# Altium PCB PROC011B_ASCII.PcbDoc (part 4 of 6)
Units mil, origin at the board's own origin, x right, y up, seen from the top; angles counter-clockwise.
Board outline 3304 x 2569 mil, 6 copper layers (TOP, L2-GND1, L3-GND/SIG, L4-GND/SIG, L5-GND2, BOTTOM), stack 55.77 mil thick; 376 components, 289 nets, 1284 pads, 1755 vias.
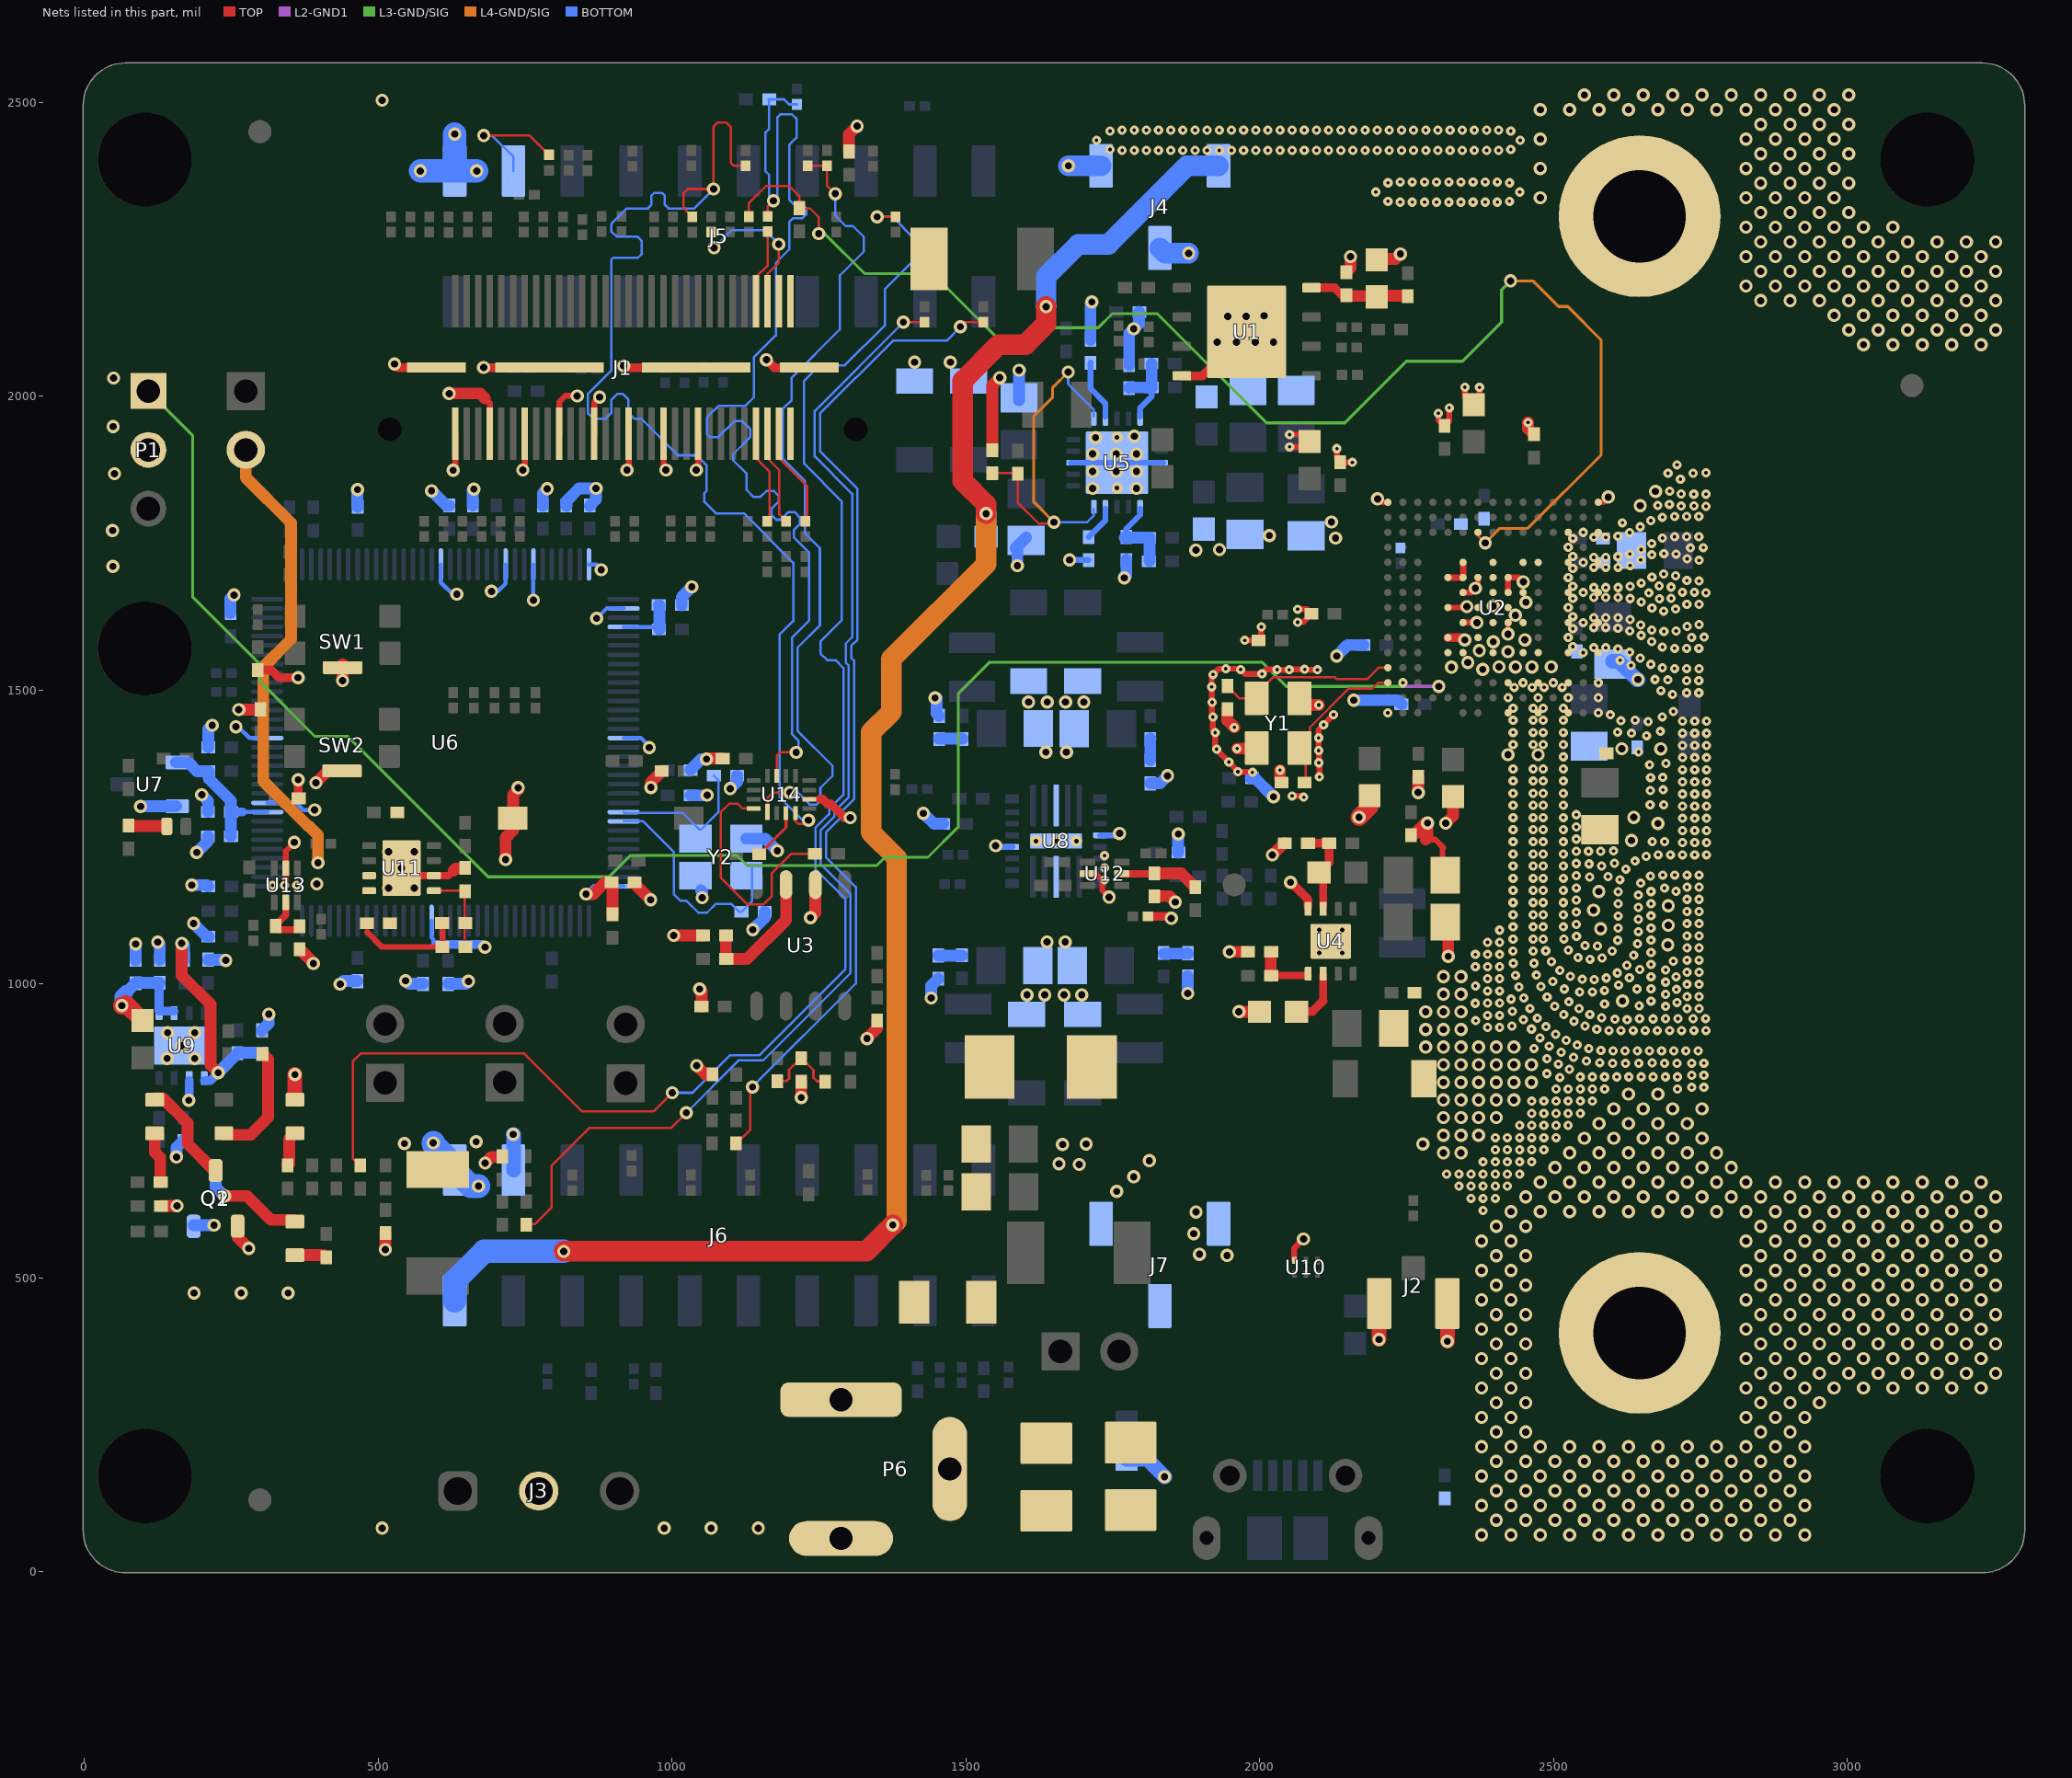
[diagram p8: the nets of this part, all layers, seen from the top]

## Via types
v1: diameter 22.4, hole 12.2, TOP to BOTTOM, tented both sides, 1046 vias
v2: diameter 15.74, hole 5.9, TOP to L2-GND1, tented both sides, 700 vias
v3: diameter 19.68, hole 7.87, TOP to BOTTOM, tented both sides, 9 vias

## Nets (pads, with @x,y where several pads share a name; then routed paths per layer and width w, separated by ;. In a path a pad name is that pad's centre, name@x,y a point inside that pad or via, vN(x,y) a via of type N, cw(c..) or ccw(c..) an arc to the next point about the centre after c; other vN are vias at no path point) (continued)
AR_VSENSE: P1.1 U2.C14 | length 3095.5
  L2-GND1 w5: v2(2243.76,1512.45) 2249.91,1506.3 v1(2304.85,1506.3)
  L3-GND/SIG w5: P1.1@109.02,2008.65 184.25,1933.42 184.25,1658.5 297.95,1544.8 297.95,1515.3 391.75,1421.5 447.65,1421.5 686.85,1182.3 893.05,1182.3 929.45,1218.7 1079.78,1218.7 1079.92,1218.56 1110.25,1218.56 1127.41,1201.4 1348.65,1201.4 1362.72,1215.47 1435.53,1215.47 1487.45,1267.39 1487.45,1494.47 1540.13,1547.15 2004.69,1547.15 2045.54,1506.3 v1(2304.85,1506.3)
AR_WARMRST: R15.1 R18.1 U2.N9 | length 2374.3
  TOP w4: R18.1@1130.96,2305.56 1130.96,2328.72 1159.74,2357.5 1199.74,2357.5 1216.75,2340.49 R15.1@1216.75,2320.04 1216.75,2319.25 1234.99,2319.25 1249.75,2304.49 v1(1249.75,2276.5) ; U2.N9@2371.71,1768.35 2371.71,1762.58 v1(2383.94,1750.35)
  L3-GND/SIG w5: v1(1249.75,2276.5) 1259.75,2276.5 1327.75,2208.5 1443.74,2208.5 1511.74,2140.5 1561.75,2090.5 1624.55,2090.5 1650.75,2116.7 1725.55,2116.7 1749.35,2140.5 1825.65,2140.5 2011.65,1954.5 2144.85,1954.5 2249.85,2059.5 2345.25,2059.5 2411.75,2126 2411.75,2181 v1(2426.95,2196.2)
  L4-GND/SIG w5: v1(2383.94,1750.35) 2408.69,1775.1 2456.15,1775.1 2581.15,1900.1 2581.15,2095.7 2524.35,2152.5 2508.95,2152.5 2465.25,2196.2 v1(2426.95,2196.2)
AR_XTALM: C9.2 U2.D15 Y1.1 | length 310.5
  TOP w4: C9.2@1945.11,1506.53 1965.68,1485.96 Y1.1@1995.05,1485.96 1995.05,1494.1 2022.55,1521.6 2128.25,1521.6 2131.35,1518.5 2182.76,1518.5 2202.3,1538.04 U2.D15@2218.17,1538.04
AR_XTALP: C15.2 U2.C15 Y1.3 | length 269.3
  TOP w4: C15.2@2078.45,1342.9 2078.28,1343.07 2078.28,1390.93 Y1.3@2067.89,1401.32 2085.45,1418.88 2085.45,1436.2 2151.75,1502.5 2191.75,1502.5 2201.7,1512.45 U2.C15@2218.17,1512.45
CAN_RX: R12.1 U14.3 | length 88.9
  TOP w5: R12.1@1148.6,1220.7 1148.6,1220.88 1194.14,1266.43 U14.3@1194.14,1290.71
CAN_TX: R11.1 U14.16 | length 414.6
  TOP w4: U14.16@1139.03,1298.59 1119.85,1298.59 1111.77,1306.66 1097.53,1306.66 1082.75,1291.88 1082.75,1181.16 1128.82,1135.09 1155.63,1135.09 1170.22,1149.68 1170.22,1188.61 1203.03,1221.42 R11.1@1243.26,1221.42
CS1: R1.2 R14.1 R17.1 U14.11 | length 2014.1
  TOP w4: R17.1@1163,2306.21 1163,2322.75 v1(1172.75,2332.5) ; U14.11@1178.4,1353.71 1178.4,1388.61 1183.82,1394.03 v1(1211.3,1394.03)
  BOTTOM w4: R14.1@1164.55,2505.1 1164.94,2504.71 R14.1@1165.33,2504.32 ; v1(1211.3,1394.03) 1215.55,1398.28 1215.55,1413.8 1204.58,1424.77 1204.58,1589.33 1233.65,1618.4 1233.65,1733.6 1207.37,1759.88 1207.37,1771.75 1217.45,1781.83 1217.45,1793.84 1208.44,1802.85 1198.4,1802.85 1185.43,1789.88 1177.37,1789.88 1169.46,1797.79 1169.46,1808.62 1181.52,1820.68 1181.52,1830.71 1173.46,1838.77 1160.66,1838.77 1150.25,1828.36 1138.89,1828.36 1126.93,1840.32 1126.93,1867.97 1104.17,1890.73 1104.17,1901.36 1133.26,1930.45 1133.26,1943.7 1118.91,1958.05 1106.58,1958.05 1079.08,1930.56 1064.35,1930.56 1059.53,1935.37 1059.53,1964.01 1079.32,1983.8 1125.15,1983.8 1139.72,1998.38 1139.72,2066.57 1176.75,2103.6 1176.75,2226.9 1199.45,2249.6 1199.45,2295.83 1206.59,2302.97 1222.11,2302.97 1228.57,2309.43 1228.57,2319.78 1221.17,2327.18 1206.59,2327.18 1199.45,2334.32 1199.45,2427.51 1212.05,2440.11 1212.05,2471.94 1204.37,2479.62 1184.3,2479.62 1179.41,2474.73 1179.41,2339.16 v1(1172.75,2332.5) 1165.33,2339.92 1165.33,2376.39 1159.09,2382.63 1159.09,2448.81 1165.33,2455.05 R14.1@1165.33,2504.32 ; R14.1@1165.33,2504.32 R14.1@1165.33,2505.1 1190.75,2505.1 1199.34,2496.51 ; 1199.34,2496.51 R1.2@1212.55,2496.51 1199.34,2496.51
D_LOGGER: J5.4 R60.1 | length 214.1
  TOP w4: v1(679.75,2443.5) 757.74,2443.5 R60.1@790.75,2410.49
  BOTTOM w4: v1(679.75,2443.5) 693.75,2443.5 730.25,2407 J5.4@730.25,2383.22
GND: C1.1 C2.1 C3.1 C4.1 C5.1 C6.1 C7.1 C8.1 C9.1 C10.1 C11.1 C12.1 C13.1 C14.1 C15.1 C16.1 C17.1 C19.1 C20.1 C21.1 C22.1 C23.1 C24.1 C25.1 C26.2 C27.2 C29.1 C30.1 C31.1 C32.1 C33.1 C34.1 C35.1 C36.1 C37.1 C38.1 C39.1 C40.1 C41.1 C42.1 C43.1 C44.1 C45.1 C47.1 C48.1 C49.1 C50.1 C51.1 C52.1 C53.1 C54.1 C55.1 C56.1 C57.1 C58.1 C59.1 C60.1 C61.1 C62.1 C63.1 C64.1 C65.1 C66.1 C67.1 C68.1 C69.1 C70.1 C71.1 C72.1 C73.1 C74.1 C75.1 C76.1 C77.1 C79.1 C80.1 C81.1 C82.1 C83.1 C84.1 C85.1 C86.1 C87.1 C89.1 C90.1 C91.1 C92.1 C93.1 C94.1 C95.1 C96.1 C97.1 D3.2 DS2.2 J1.18 J1.24 J1.30 J1.36 J1.42 J1.48 J1.54 J1.60 J1.MP1 J1.MP2 J1.MP3 J1.MP4 J2.2 J2.3 J3.2 J4.1 J4.2 J5.2 J6.4 J7.1 J7.2 P1.2 P6.2 P6.3 pad.1 pad.2 Q1.2 Q2.2 R13.1 R47.2 R73.1 R79.1 R81.1 R83.2 R86.2 R88.1 R96.1 R110.1 R114.1 R119.1 R121.1 R123.2 R125.1 R126.2 R132.1 R138.1 R139.1 R153.1 R157.1 R158.1 R167.1 R174.1 R175.1 R193.1 R208.2 S2.1 SW1.5 SW2.5 U1.4 U1.9 U2.A1 U2.A3 U2.A5 U2.A7 U2.A15 U2.B1 U2.B3 U2.B5 U2.B7 U2.C1 U2.C3 U2.C4 U2.C5 U2.C6 U2.C7 U2.E1 U2.E2 U2.E3 U2.E5 U2.E6 U2.E8 U2.E10 U2.E11 U2.F3 U2.F9 U2.F11 U2.G1 U2.G2 U2.G3 U2.G6 U2.G7 U2.G8 U2.G10 U2.H3 U2.H7 U2.H9 U2.H11 U2.J1 U2.J2 U2.J3 U2.J6 U2.J7 U2.J8 U2.J10 U2.K3 U2.K7 U2.K8 U2.K9 U2.K10 U2.K11 U2.L1 U2.L2 U2.L3 U2.L5 U2.L6 U2.L8 U2.L10 U2.M3 U2.N1 U2.N2 U2.N3 U2.R1 U2.R15 U3.2 U4.4 U4.9 U5.3 U5.13 U5.21@1757.37,1886.82 U6.10 U6.17 U6.48 U6.55 U6.58 U6.64 U6.66 U6.80 U6.114 U7.2 U8.4 U8.11 U8.17 U8.24 U8.27 U9.6 U9.9 U10.3 U11.6 U11.9 U12.2 U13.2 U14.6 Y1.2 Y1.4 Y2.2 Y2.4 | length 8140.2
  TOP w7: U14.6@1233.51,1314.34 1252.42,1314.34 ; U2.J7@2421.64,1665.99 U2.J7@2422.89,1665.99 U2.J7@2423.36,1665.99 ; U2.G7@2422.89,1614.81 U2.G7@2422.89,1614.81 v1@2422.89,1595.21
  TOP w9: v1(2367.2,1673.3) 2371.71,1677.81 U2.K9@2371.71,1691.58
  TOP w10: v2@342.75,1175.5 342.75,1226.3 v1(357.35,1240.9) ; v1(627.73,1874.03) 631.37,1877.67 J1.60@631.37,1935.77 ; 681.75,1996.5 690.42,1987.83 J1.54@690.42,1935.77 ; v1(746.28,1874.47) 749.48,1877.67 J1.48@749.48,1935.77 ; J1.42@808.53,1935.77 808.53,1990.5 818.53,2000.5 v1(838.75,2000.5) ; J1.36@867.59,1935.77 867.59,1989.34 v1(876.75,1998.5) ; v1(923.36,1874.39) 926.64,1877.67 J1.30@926.64,1935.77 ; J1.24@985.7,1935.77 985.7,1878.55 v1(989.75,1874.5) ; v1(1041.42,1874.34) 1044.75,1877.67 J1.18@1044.75,1935.77 ; U12.2@1707.12,1187.4 1720.95,1187.4 1732.15,1176.2 1732.15,1159.4 v1(1743.95,1147.6) ; v2(1974.75,1584.5) C84.1@1998.07,1584.5 1998.45,1584.5 2002.75,1588.8 v2(2002.75,1607.5) ; v2(1987.75,1360) 1987.75,1360.9 v2(1962.85,1360.9) 1962.85,1362.4 v2(1947.75,1377.5) 1926.75,1398.5 v2(1926.75,1399.5) 1924.35,1401.9 v2(1924.35,1427.5) 1920.45,1431.4 v2(1920.45,1454) 1919.05,1455.4 v2(1919.05,1479.1) 1919.05,1504.8 v2(1918.45,1505.4) 1918.45,1524.2 v2(1920.75,1526.5) 1930.65,1536.4 v2(1942.45,1536.4) 1966.35,1536.4 v2(1967.75,1535) 1975.35,1527.4 v2(2004.05,1527.4) 2011.55,1534.9 v2(2029.75,1534.9) 2030.15,1534.5 v2(2050.35,1534.5) 2051.18,1535.33 v2(2076.77,1535.33) 2077.7,1534.4 2098.45,1534.4 v2(2098.55,1534.5) ; v2(2051.05,1913.8) 2075.75,1913.8 C89.1@2084.85,1922.9 2073.15,1934.6 v2(2051.05,1934.6) ; v2(2055.37,1319.8) 2073.05,1319.8 v2(2075.15,1317.7) ; U10.3@2059.07,529.81 2059.06,550.31 v1(2074.75,566) ; v2(2064.75,1615.5) 2074.07,1615.5 2088.42,1629.85 2080.77,1637.5 v2(2064.75,1637.5) ; v2(2101.85,1352.2) 2101.85,1375.3 v2(2100.85,1376.3) 2100.85,1396.5 v2(2100.45,1396.9) v2(2100.45,1418.6) 2100.45,1432.5 v2(2108.95,1441) v2(2125.9,1457.95) ; v2(2131.55,1910.8) 2131.55,1893.1 2137.25,1887.4 v2(2158.05,1887.4) ; v1(2200.75,1825.3) 2206.52,1819.53 U2.R15@2218.17,1819.53 ; C90.1@2261.63,1253.2 2275.05,1253.2 2282.75,1245.5 2298.85,1245.5 2312.55,1231.8 2311.25,1230.5 C17.1@2311.25,1185.1 ; v2(2304.15,1970.9) 2304.15,1959.4 2314.15,1949.4 2314.7,1949.4 2322.65,1957.35 v2(2322.65,1980.3) ; U2.H11@2320.53,1640.4 2351.3,1640.4 v1(2352.8,1641.9) ; U2.G10@2346.12,1614.81 v1@2369.69,1614.81 ; U2.J10@2346.12,1665.99 2359.89,1665.99 v1(2367.2,1673.3) ; v2(2349.35,2015.2) 2349.35,2000.05 2364,1985.4 C87.1@2364.55,1985.4 2374.25,1995.1 v2(2374.25,2015) ; U2.J7@2422.89,1665.99 U2.K7@2422.89,1691.58 2441.17,1691.58 v1(2448.75,1684) ; U2.R1@2576.43,1819.53 2584.43,1819.53 v1(2593.3,1828.4)
  TOP w11: U2.K11@2320.53,1691.58 U2.K10@2346.12,1691.58 U2.L10@2346.12,1717.17
  TOP w12: v1(539.65,1197) 552.45,1184.2 619.65,1184.2 628.45,1193
  TOP w15: R73.1@294.8,1534.52 317.73,1534.52 331.25,1521 v1(363.75,1521) ; R79.1@363.9,1315.64 v1(363.9,1347.5) ; v1(527.95,2054.8) 533.99,2048.76 J1.MP4@598.87,2048.76 J1.MP4@599.48,2048.76 ; v1(679.51,2048.76) J1.MP3@791.39,2048.76 J1.MP3@792,2048.76 ; v1(917.75,2051.5) 920.49,2048.76 J1.MP2@1041.39,2048.76 J1.MP2@1042,2048.76 ; v1(1160.75,2062) 1173.99,2048.76 J1.MP1@1233.91,2048.76 J1.MP1@1234.52,2048.76 ; 1252.42,1314.34 1256.5,1314.34 1264.61,1306.23 1270.12,1306.23 1293.63,1282.72 v1(1303.33,1282.72) ; R167.1@1810.34,1115.1 1846.25,1115.1 v1(1849.75,1111.6) ; U1.4@1865.68,2034.68 U1.4@1867.64,2034.68 1902.88,2034.68 U1.9@1977.88,2109.68 ; v1(2052.75,1173) 2082.54,1143.21 U4.4@2082.54,1130.54 ; U2.F11@2320.53,1589.22 2345.08,1589.22 v1(2349.1,1585.2)
  TOP w20: R110.1@129.37,622.27 R110.1@130.15,622.27 v1(157.75,622.27) ; Q1.2@260.73,589.97 260.73,569.02 v1(279.75,550) ; v1(262.75,1466.7) C11.1@300.05,1466.7 ; C92.1@366.35,1059.4 389.85,1035.9 v1(389.85,1034.8) ; v1(393.95,1342.2) 414.15,1362.4 SW2.5@438.45,1362.4 ; v1(439.4,1516) SW1.5@439.4,1538.02 SW1.5@439.4,1543.92 ; v1(512.27,548) R114.1@512.27,575.96 R114.1@512.27,576.75 ; v1(620.75,2004.5) 673.75,2004.5 681.75,1996.5 ; 628.45,1193 631.86,1196.41 R193.1@647.65,1196.41 ; v1(681.95,695) 692.6,705.65 R96.1@711.53,705.65 ; v1(716.81,1211.5) 716.81,1248.73 729.68,1261.6 729.68,1322.06 738.15,1330.53 v1(738.15,1333.88) ; C71.1@936.05,1173 936.05,1170.7 v1(963.75,1143) ; v1(964.01,1334.23) 964.01,1342.99 982.54,1361.53 C97.1@982.54,1361.93 ; v1(1002.75,1082.5) C16.1@1052.67,1082.5 C16.1@1053.05,1082.5 ; v1(1041.95,861.1) 1057.8,845.25 R88.1@1068.87,845.25 ; v1(1047.05,991.4) 1050.64,987.81 C20.1@1050.64,961.35 ; v1(1058.77,1382.5) 1059.89,1383.62 R208.2@1086.13,1383.62 ; v1(1219.85,806.6) C24.1@1219.85,833.92 C24.1@1219.85,834.3 ; v1(1235.75,1112.5) 1244.06,1120.81 U3.2@1244.06,1168.83 U3.2@1244.06,1169.81 ; R13.1@1301.15,2415.45 R13.1@1301.15,2416.24 1301.15,2445.5 v1(1315.15,2459.5) ; v1(1331.75,907) 1349.05,924.3 R86.2@1349.05,937.51 R86.2@1349.05,938.3 ; R47.2@1545.15,1907.3 R47.2@1545.15,1908.09 1545.15,2018.8 v1(1557.85,2031.5) ; C91.1@1821.15,1149.3 1846.45,1149.3 v1(1856.55,1139.2) ; C9.1@1945.11,1467.93 C9.1@1945.11,1467.54 1945.11,1448.44 v2(1957.05,1436.5) ; v1(1948.75,1054.52) R83.2@1980.41,1054.52 R83.2@1981.2,1054.52 ; v2(1961.75,1400.5) 1994.23,1400.5 Y1.2@1995.05,1401.32 ; v1(1964.75,952.77) C22.1@1999.72,952.77 ; v1(2021.75,1219.5) 2041.92,1239.67 R81.1@2042.96,1239.67 R81.1@2043.74,1239.67 ; C15.1@2034.75,1348 v2(2034.75,1363.8) ; Y1.4@2067.89,1485.96 2079.35,1474.5 v2(2100.75,1474.5) ; C2.1@2147.65,2210.7 C2.1@2147.65,2211.08 2154.75,2218.18 v1(2154.75,2237.5) ; C1.1@2199.35,2233.6 2231.15,2233.6 v1(2239.55,2242) ; C90.1@2257.75,1252.82 2261.25,1252.82 2261.63,1253.2 2282.23,1273.8 v1(2285.85,1273.8) 2285.85,1248.6 2282.75,1245.5 ; v1(2269.95,1325.6) C12.1@2269.95,1352.01 C12.1@2269.95,1352.4 ; C19.1@2311.1,1105.17 2321.05,1095.22 v1(2321.05,1046.7) ; v1(2316.75,1273.4) 2329.25,1285.9 C13.1@2329.25,1318.9 ; v2(2456.95,1955.3) 2456.95,1944.75 2466.95,1934.75 C3.1@2466.95,1935.14
  TOP w25: DS2.2@358.35,805.87 v1(358.35,845.9) ; v1(2203.39,395) J2.2@2203.39,456.22 ; v1(2319.53,392) J2.3@2319.53,456.22
  TOP w30: v1(2169.35,1283.5) 2187.2,1301.35 C14.1@2187.2,1320.4
  BOTTOM w7: v1(257.75,1437.5) 261.75,1437.5 280.84,1418.41 U6.17@311.39,1418.41 ; U6.10@311.39,1308.18 360.75,1308.18 373.53,1295.4 391.15,1295.4 391.15,1296.1 v1(391.85,1296.1) ; U6.114@590.92,1107.39 590.92,1078.73 594.15,1075.5 594.25,1075.5 594.25,1071 597.95,1067.3 ; U6.48@606.67,1713.69 606.67,1683.09 626.76,1663 v1(633.75,1663) ; v1(692.75,1668) 703.75,1668 716.9,1681.15 U6.55@716.9,1713.69 ; v1(764.15,1652.8) U6.58@764.15,1713.69 ; U6.64@858.63,1713.69 871.75,1713.69 879.75,1705.69 v1(879.75,1704.5) ; v1(871.75,1622) 888.64,1638.89 U6.66@917.69,1638.89 ; U6.80@917.69,1418.41 947.24,1418.41 v1@963.61,1402.04 ; v1(961.45,1402.04) v1@963.61,1402.04 ; v1@967.75,1397.9 v1@963.61,1402.04
  BOTTOM w10: v1(1550.85,1235) 1551.3,1235 1551.3,1235.05 1553.19,1233.16 U8.4@1578.95,1233.16 ; v1(1676.75,1721.45) C44.1@1708.92,1721.45 ; U5.3@1682.57,1886.82 U5.3@1678.63,1886.82 ; U5.21@1715.95,1886.82 U5.3@1678.63,1886.82 ; U8.17@1728.55,1252.84 1758.59,1252.84 v1(1761.75,1256) ; U5.21@1755.95,1886.82 U5.3@1678.63,1886.82 ; U5.21@1757.37,1886.82 U5.3@1678.63,1886.82 ; U5.21@1790.45,1886.82 U5.3@1678.63,1886.82 ; U5.13@1836.11,1886.82 U5.3@1678.63,1886.82
  BOTTOM w15: v1(177.75,802) 178.38,802 U9.6@178.38,835.82 ; 597.95,1067.3 677.05,1067.3 v1(681.85,1062.5)
  BOTTOM w20: C80.1@87.35,1040.3 C80.1@87.35,1040.68 v1(87.35,1068) ; v1(95.75,1302) 100.75,1302 100.75,1302.19 U7.2@156.11,1302.19 ; v1(124.75,1071) 128.37,1067.38 C79.1@128.37,1041.04 C79.1@128.37,1040.65 ; v1(156.75,705.5) 156.75,721.77 R158.1@168.43,733.45 ; v1(182.75,1168) 207.75,1168 209.69,1166.06 C69.1@210.71,1166.06 C69.1@211.1,1166.06 ; v1(185.75,1103) 208.51,1080.24 R153.1@210.71,1080.24 R153.1@211.5,1080.24 ; Q2.2@185.97,589.39 v1(220.75,589.39) ; v1(191.15,1223.6) 210.7,1243.15 C67.1@210.7,1251.3 ; v1(199.75,1322) 210.64,1311.11 C66.1@210.64,1292.6 ; C77.1@210.57,1040.95 236.75,1040.95 236.75,1040 v1(240.75,1040) ; C61.1@211.1,1402.56 211.1,1433.65 v1(217.45,1440) ; C50.1@248.7,1630.5 C50.1@248.7,1630.89 248.7,1655.65 v1(254.75,1661.7) ; R157.1@301.95,920.25 R157.1@301.95,921.04 313.75,932.83 v1(313.75,948.5) ; v1(435.35,999.4) 441,1005.05 C76.1@464.67,1005.05 ; v1(464.75,1841) 464.48,1840.73 464.48,1812.44 C43.1@465.27,1811.65 ; v1(546.75,1005.5) 551.9,1000.35 C75.1@576.43,1000.35 ; v1(590.75,1839) 616.1,1813.65 C42.1@620.97,1813.65 ; C74.1@619.35,1000.35 649.6,1000.35 v1(653.65,1004.4) ; C41.1@661.05,1813.65 C41.1@661.05,1814.04 661.05,1840.3 v1(662.75,1842) ; R125.1@780.27,1813.25 R125.1@780.27,1814.04 780.27,1835.02 v1(787.75,1842.5) ; R126.2@820.43,1813.55 R126.2@820.43,1814.34 820.43,1821.68 841.75,1843 v1(870.75,1843) 870.75,1824.27 R123.2@860.03,1813.55 ; C49.1@1016.4,1644.4 1016.4,1658.15 v1(1033.75,1675.5) ; C62.1@1031.4,1364 1049.9,1382.5 v1(1058.77,1382.5) ; C64.1@1031.7,1320.8 C64.1@1032.08,1320.8 1058.75,1320.8 1058.75,1321 v1(1059.75,1321) ; 1049.4,1159 1051.36,1157.04 v1(1051.36,1146.57) ; v1(1099.01,1332.3) 1110.68,1343.97 C63.1@1110.68,1354.35 ; Y2.2@1126.7,1247.08 1158.57,1247.08 v1(1179.2,1226.45) ; v1(1137.41,1092.2) 1157.62,1112.42 C70.1@1157.62,1122.7 ; v1(1427.8,1290.35) 1445.75,1272.4 R138.1@1461.17,1272.4 R138.1@1461.95,1272.4 ; v1(1441,975.95) 1441,996.86 C95.1@1453.15,1009.01 C95.1@1453.15,1009.4 ; v1(1447.75,1486.5) 1450.45,1486.5 1450.45,1460.08 C93.1@1454.45,1456.08 C93.1@1454.45,1455.7 ; v1(1587.75,1711.5) 1587.75,1738.45 1584.75,1741.45 C40.1@1602.7,1759.4 ; C32.1@1590.7,1992.9 C32.1@1590.7,1997.5 v1(1590.7,2044.2) ; C29.1@1712.22,2095.85 C29.1@1712.22,2096.24 1712.22,2158.17 v1(1714.45,2160.4) ; v1(1769.75,1691) 1773.22,1694.47 R132.1@1773.22,1721.17 R132.1@1773.22,1721.95 ; R121.1@1778.02,2052.29 R121.1@1778.02,2053.07 1778.02,2106.62 v1(1785.9,2114.5) 1794.65,2123.25 R119.1@1794.65,2143.5 ; C94.1@1814.05,1341.5 1830.55,1341.5 v1(1843.25,1354.2) ; C68.1@1861.5,1223.5 1861.5,1255 v1(1861.75,1255) ; v1(1877.85,983.8) C96.1@1877.85,1012.92 C96.1@1877.85,1013.3 ; R139.1@1985,1350.04 R139.1@1987.43,1350.04 1992.11,1350.04 v1(2023.7,1318.45) ; v1(2131.25,1558) 2149.75,1576.5 C53.1@2176.42,1576.5 C53.1@2176.8,1576.5 ; v1(2160.35,1482.6) 2234.8,1482.6 C56.1@2241.6,1475.8
  BOTTOM w25: v1(729.75,744) 730.25,744 J6.4@730.25,683.22 ; R175.1@1773.75,191.5 1808.25,191.5 v1(1838.25,161.5) ; C52.1@2600.9,1548.5 2611.55,1548.5 2642.25,1517.8 v1(2643.85,1517.8)
  BOTTOM w35: v1(1674.77,2391.98) J4.1@1730.25,2391.98 ; J4.2@1830.25,2252.02 1839.17,2243.1 v1(1879.35,2243.1)
  BOTTOM w40: v1(571.75,2383.22) J5.2@630.25,2383.22 ; v1(630.25,2446) J5.2@630.25,2383.22 ; v1(667.75,2383.22) J5.2@630.25,2383.22
  other v1: 2377.75,62.5 2427.75,62.5 2477.75,62.5 2527.75,62.5 2577.75,62.5 2627.75,62.5 2677.75,62.5 2727.75,62.5 2777.75,62.5 2827.75,62.5 2877.75,62.5 2927.75,62.5 506.75,74 986.75,74 1066.75,74 1146.75,74 2402.75,87.5 2452.75,87.5 2502.75,87.5 2552.75,87.5 2602.75,87.5 2652.75,87.5 2702.75,87.5 2752.75,87.5 2802.75,87.5 2852.75,87.5 2902.75,87.5 2377.75,112.5 2427.75,112.5 2477.75,112.5 2527.75,112.5 2577.75,112.5 2627.75,112.5 2677.75,112.5 2727.75,112.5 2777.75,112.5 2827.75,112.5 2877.75,112.5 2927.75,112.5 2402.75,137.5 2452.75,137.5 2502.75,137.5 2552.75,137.5 2602.75,137.5 2652.75,137.5 2702.75,137.5 2752.75,137.5 2802.75,137.5 2852.75,137.5 2902.75,137.5 2377.75,162.5 2427.75,162.5 2477.75,162.5 2527.75,162.5 2577.75,162.5 2627.75,162.5 2677.75,162.5 2727.75,162.5 2777.75,162.5 2827.75,162.5 2877.75,162.5 2927.75,162.5 2402.75,187.5 2452.75,187.5 2502.75,187.5 2552.75,187.5 2602.75,187.5 2652.75,187.5 2702.75,187.5 2752.75,187.5 2802.75,187.5 2852.75,187.5 2902.75,187.5 2377.75,212.5 2427.75,212.5 2477.75,212.5 2527.75,212.5 2577.75,212.5 2627.75,212.5 2677.75,212.5 2727.75,212.5 2777.75,212.5 2827.75,212.5 2877.75,212.5 2927.75,212.5 2402.75,237.5 2452.75,237.5 2852.75,237.5 2902.75,237.5 2377.75,262.5 2427.75,262.5 2827.75,262.5 2877.75,262.5 2927.75,262.5 2402.75,287.5 2452.75,287.5 2852.75,287.5 2902.75,287.5 2952.75,287.5 2377.75,312.5 2427.75,312.5 2827.75,312.5 2877.75,312.5 2927.75,312.5 2977.75,312.5 3027.75,312.5 3077.75,312.5 3127.75,312.5 3177.75,312.5 3227.75,312.5 2402.75,337.5 2452.75,337.5 2852.75,337.5 2902.75,337.5 2952.75,337.5 3002.75,337.5 3052.75,337.5 3102.75,337.5 3152.75,337.5 3202.75,337.5 3252.75,337.5 2377.75,362.5 2427.75,362.5 2827.75,362.5 2877.75,362.5 2927.75,362.5 2977.75,362.5 3027.75,362.5 3077.75,362.5 3127.75,362.5 3177.75,362.5 3227.75,362.5 2402.75,387.5 2452.75,387.5 2852.75,387.5 2902.75,387.5 2952.75,387.5 3002.75,387.5 3052.75,387.5 3102.75,387.5 3152.75,387.5 3202.75,387.5 3252.75,387.5 2377.75,412.5 2427.75,412.5 2827.75,412.5 2877.75,412.5 2927.75,412.5 2977.75,412.5 3027.75,412.5 3077.75,412.5 3127.75,412.5 3177.75,412.5 3227.75,412.5 2402.75,437.5 2452.75,437.5 2852.75,437.5 2902.75,437.5 2952.75,437.5 3002.75,437.5 3052.75,437.5 3102.75,437.5 3152.75,437.5 3202.75,437.5 3252.75,437.5 2377.75,462.5 2427.75,462.5 2827.75,462.5 2877.75,462.5 2927.75,462.5 2977.75,462.5 3027.75,462.5 3077.75,462.5 3127.75,462.5 3177.75,462.5 3227.75,462.5 186.75,474 266.75,474 346.75,474 2402.75,487.5 2452.75,487.5 2852.75,487.5 2902.75,487.5 2952.75,487.5 3002.75,487.5 3052.75,487.5 3102.75,487.5 3152.75,487.5 3202.75,487.5 3252.75,487.5 2377.75,512.5 2427.75,512.5 2827.75,512.5 2877.75,512.5 2927.75,512.5 2977.75,512.5 3077.75,512.5 3127.75,512.5 3177.75,512.5 3227.75,512.5 3026.75,514 2402.75,537.5 2452.75,537.5 2852.75,537.5 2902.75,537.5 2952.75,537.5 3002.75,537.5 3052.75,537.5 3102.75,537.5 3152.75,537.5 3202.75,537.5 3252.75,537.5 2377.75,562.5 2427.75,562.5 2827.75,562.5 2877.75,562.5 2927.75,562.5 2977.75,562.5 3027.75,562.5 3077.75,562.5 3127.75,562.5 3177.75,562.5 3227.75,562.5 2402.75,587.5 2452.75,587.5 2852.75,587.5 2902.75,587.5 2952.75,587.5 3002.75,587.5 3052.75,587.5 3102.75,587.5 3152.75,587.5 3202.75,587.5 3252.75,587.5 2427.75,612.5 2477.75,612.5 2527.75,612.5 2577.75,612.5 2627.75,612.5 2677.75,612.5 2727.75,612.5 2777.75,612.5 2827.75,612.5 2877.75,612.5 2927.75,612.5 2977.75,612.5 3027.75,612.5 3077.75,612.5 3127.75,612.5 3177.75,612.5 3227.75,612.5 2452.75,637.5 2502.75,637.5 2552.75,637.5 2602.75,637.5 2652.75,637.5 2702.75,637.5 2752.75,637.5 2802.75,637.5 2852.75,637.5 2902.75,637.5 2952.75,637.5 3002.75,637.5 3052.75,637.5 3102.75,637.5 3152.75,637.5 3202.75,637.5 3252.75,637.5 1756.85,647 2477.75,662.5 2527.75,662.5 2577.75,662.5 2627.75,662.5 2677.75,662.5 2727.75,662.5 2777.75,662.5 2827.75,662.5 2877.75,662.5 2927.75,662.5 2977.75,662.5 3027.75,662.5 3077.75,662.5 3127.75,662.5 3177.75,662.5 3227.75,662.5 1785.65,671.8 2502.75,687.5 2552.75,687.5 2602.75,687.5 2652.75,687.5 2702.75,687.5 2752.75,687.5 2802.75,687.5 1693.05,692.7 1658.75,693.9 1812.35,699.2 2312.75,712.5 2342.75,712.5 2527.75,712.5 2577.75,712.5 2627.75,712.5 2677.75,712.5 2727.75,712.5 2777.75,712.5 1664.65,726.9 1704.75,727.6 2277.75,727.5 2552.75,737.5 2602.75,737.5 2652.75,737.5 2702.75,737.5 2752.75,737.5 2312.75,742.5 2342.75,742.5 2372.75,742.5 2577.75,762.5 2627.75,762.5 2677.75,762.5 2727.75,762.5 2312.75,772.5 2342.75,772.5 2372.75,772.5 2402.75,772.5 2602.75,787.5 2652.75,787.5 2702.75,787.5 2752.75,787.5 2312.75,802.5 2342.75,802.5 2372.75,802.5 2402.75,802.5 2432.75,802.5 2627.75,812.5 2677.75,812.5 2312.75,832.5 2342.75,832.5 2372.75,832.5 2402.75,832.5 2432.75,832.5 2462.75,832.5 2312.75,862.5 2342.75,862.5 2372.75,862.5 2402.75,862.5 2432.75,862.5 2462.75,862.5 140.75,873 187.75,873 2282.75,892.5 2312.75,892.5 2342.75,892.5 2372.75,892.5 2402.75,892.5 2432.75,892.5 165.58,894.88 141.75,917 187.75,917 2282.75,922.5 2312.75,922.5 2342.75,922.5 2282.75,952.5 2312.75,952.5 2342.75,952.5 2617.65,970.8 1604.3,981.3 1634.3,981.3 1667.3,981.3 1697.3,981.3 2312.75,982.5 2342.75,982.5 2312.75,1012.5 2342.75,1012.5 2694.55,1066.4 1638.3,1071.3 1669.3,1071.3 2580.45,1093.9 2695.45,1099.6 2568.45,1125.4 2695.45,1133 2577.15,1157.3 517.65,1163 561.65,1163 517.65,1225 561.65,1225 2632.95,1243.9 2677.85,1273 2636.65,1283.4 2422.89,1389.89 2474.07,1389.9 1636.3,1394.3 1671.3,1394.3 2616.55,1400.1 2682.75,1400 1606.75,1479.5 1638.75,1479.5 1669.75,1479.5 1700.75,1479.5 2379.85,1535 2326.55,1538.9 2435.5,1539.3 2463.5,1539.3 2407.5,1539.5 2496.35,1539.5 2354.35,1546.8 2422.9,1565.2 2373.95,1567 2397.8,1582.2 2451.5,1585.4 2422.9,1595.2 2369.7,1614.8 2435.35,1627.3 2397.8,1642.9 2453.2,1649.3 48.45,1710.4 1891.65,1738 1931.75,1739 2129.15,1758.6 2016.55,1763 47.95,1771.6 2122.35,1786 2647.75,1813.7 2673.75,1838 1715.95,1843.05 1790.45,1843.05 51.25,1868.1 1715.95,1872.05 1755.95,1872.05 1790.45,1872.05 1715.95,1901.55 1755.95,1901.55 1790.45,1901.55 1720.75,1929.5 1786.75,1932 49.05,1948.4 49.85,2030.8 1412.95,2058 1473.75,2058 3027.75,2087.5 3077.75,2087.5 3127.75,2087.5 3177.75,2087.5 3227.75,2087.5 1927.75,2091.8 1960.75,2091.8 1992.75,2091.8 2023.75,2091.8 3002.75,2112.5 3052.75,2112.5 3102.75,2112.5 3152.75,2112.5 3202.75,2112.5 3252.75,2112.5 1945.75,2135.8 1976.95,2135.85 2007.75,2136.8 2977.75,2137.5 3027.75,2137.5 3077.75,2137.5 3127.75,2137.5 3177.75,2137.5 3227.75,2137.5 2852.75,2162.5 2902.75,2162.5 2952.75,2162.5 3002.75,2162.5 3052.75,2162.5 3102.75,2162.5 3152.75,2162.5 3202.75,2162.5 3252.75,2162.5 2827.75,2187.5 2877.75,2187.5 2927.75,2187.5 2977.75,2187.5 3027.75,2187.5 3077.75,2187.5 3127.75,2187.5 3177.75,2187.5 3227.75,2187.5 2852.75,2212.5 2902.75,2212.5 2952.75,2212.5 3002.75,2212.5 3052.75,2212.5 3102.75,2212.5 3152.75,2212.5 3202.75,2212.5 3252.75,2212.5 2827.75,2237.5 2877.75,2237.5 2927.75,2237.5 2977.75,2237.5 3027.75,2237.5 3077.75,2237.5 3127.75,2237.5 3177.75,2237.5 3227.75,2237.5 2852.75,2262.5 2902.75,2262.5 2952.75,2262.5 3002.75,2262.5 3052.75,2262.5 3102.75,2262.5 3152.75,2262.5 3202.75,2262.5 3252.75,2262.5 2827.75,2287.5 2877.75,2287.5 2927.75,2287.5 2977.75,2287.5 3027.75,2287.5 3077.75,2287.5 2852.75,2312.5 2902.75,2312.5 2952.75,2312.5 3002.75,2312.5 2477.75,2337.5 2827.75,2337.5 2877.75,2337.5 2927.75,2337.5 2977.75,2337.5 2852.75,2362.5 2902.75,2362.5 2952.75,2362.5 3002.75,2362.5 2477.75,2387.5 2827.75,2387.5 2877.75,2387.5 2927.75,2387.5 2977.75,2387.5 2852.75,2412.5 2902.75,2412.5 2952.75,2412.5 3002.75,2412.5 2477.75,2437.5 2827.75,2437.5 2877.75,2437.5 2927.75,2437.5 2977.75,2437.5 2852.75,2462.5 2902.75,2462.5 2952.75,2462.5 3002.75,2462.5 2477.75,2487.5 2527.75,2487.5 2577.75,2487.5 2627.75,2487.5 2677.75,2487.5 2727.75,2487.5 2777.75,2487.5 2827.75,2487.5 2877.75,2487.5 2927.75,2487.5 2977.75,2487.5 506.75,2503.5 2552.75,2512.5 2602.75,2512.5 2652.75,2512.5 2702.75,2512.5 2752.75,2512.5 2802.75,2512.5 2852.75,2512.5 2902.75,2512.5 2952.75,2512.5 3002.75,2512.5
  other v2: 2380.42,614.44 2359.75,635.11 2380.42,635.11 2401.09,635.11 2339.08,655.78 2359.75,655.78 2380.42,655.78 2401.09,655.78 2421.76,655.78 2318.41,676.45 2339.08,676.45 2359.75,676.45 2380.42,676.45 2401.09,676.45 2421.76,676.45 2442.43,676.45 2380.42,697.12 2401.09,697.12 2421.76,697.12 2442.43,697.12 2463.1,697.12 2401.09,717.79 2421.76,717.79 2442.43,717.79 2463.1,717.79 2483.77,717.79 2401.09,738.46 2421.76,738.46 2442.43,738.46 2463.1,738.46 2483.77,738.46 2504.44,738.46 2442.43,759.13 2463.1,759.13 2483.77,759.13 2504.44,759.13 2525.11,759.13 2463.1,779.8 2483.77,779.8 2504.44,779.8 2525.11,779.8 2545.78,779.8 2463.1,800.47 2483.77,800.47 2504.44,800.47 2525.11,800.47 2545.78,800.47 2566.45,800.47 2504.44,821.14 2525.11,821.14 2545.78,821.14 2566.45,821.14 2587.12,821.14 2711.14,821.14 2735.46,823.96 2756.13,823.96 2511.05,841 2545.78,841.81 2566.45,841.81 2587.12,841.81 2607.79,841.81 2628.46,841.81 2649.13,841.81 2669.8,841.81 2690.47,841.81 2711.14,841.81 2735.46,844.63 2756.13,844.63 2488.95,847.3 2527.15,854.7 2508.25,863.6 2600.95,865 2622.85,864.6 2645.05,865 2688.85,864.8 2710.45,864.8 2735.46,865.23 2756.13,865.23 2578.85,866 2667.95,865.6 2556.25,869 2489.15,872.6 2534.15,875 2512.95,883.9 2601.44,885.9 2622.11,885.9 2642.78,885.9 2663.45,885.9 2684.12,885.9 2704.79,885.9 2725.46,885.9 2746.13,885.9 2580.79,886.8 2467.15,890.3 2560.35,889.9 2492.85,894.2 2540.56,895.9 2521.58,904.1 2477.15,908.3 2503.65,914.39 2594.33,920.8 2615,920.8 2635.67,920.8 2656.34,920.8 2677.01,920.8 2697.68,920.8 2718.35,920.8 2739.02,920.8 2759.69,920.8 2462.65,923.2 2573.75,922.8 2387.85,925.9 2408.55,925.9 2487.46,927.3 2429.25,928.2 2553.82,928.3 2534.84,936.5 2367.85,937.4 2448.85,939 2625.45,939 2604.65,939.8 2669.55,940.4 2646.55,941 2691.05,941 2711.85,941 2737.85,940.7 2759.15,941.1 2472.74,941.82 2582.15,942.2 2387.85,946.6 2408.55,946.6 2517.53,947.8 2562.05,948.1 2430.05,953.2 2460.25,958.3 2543.65,958 2727.24,957.83 2747.91,957.83 2502.3,961.8 2691.05,961.67 2645.85,962.6 2587.12,965.83 2367.05,967 2387.85,967.3 2408.55,967.3 2710.15,968.5 2526.15,969.5 2666.15,970.9 2428.05,974.1 2449.45,975.89 2489.25,977.83 2727.24,978.5 2747.91,978.5 2691.05,982.34 2544.65,986.1 2566.45,986.5 2387.85,988 2408.55,988 2586.95,988.9 2518.75,991.3 2642.05,991.3 2709.25,990.6 2666.15,991.6 2441.45,994.95 2367.25,996.3 2478.65,995.58 2610.95,998.2 2727.24,999.17 2747.91,999.17 2691.05,1003.01 2498.95,1004.2 2569.65,1007.3 2549.02,1007.8 2387.85,1008.7 2408.55,1008.7 2590.13,1010.1 2629.35,1010.6 2666.15,1012.3 2708.85,1012.3 2528.98,1012.9 2435.4,1014.72 2471.15,1014.85 2608.92,1018.7 2727.24,1019.84 2747.91,1019.84 2511,1022.95 2646.95,1024.5 2691.05,1023.68 2367.15,1029.4 2387.85,1029.4 2408.55,1029.4 2624.95,1031.77 2666.15,1033 2431.95,1035.11 2467.05,1035.11 2496.55,1037.91 2704.05,1038.8 2727.24,1040.51 2747.91,1040.51 2562.21,1042 2582.76,1044.3 2541.75,1044.95 2636.55,1048.87 2367.15,1050.1 2387.85,1050.1 2408.55,1050.1 2666.15,1053.7 2431.25,1055.74 2465.63,1055.74 2486.95,1056.22 2599.96,1055.8 2525.37,1057.59 2727.24,1061.18 2747.91,1061.18 2574.75,1064.5 2553.65,1065.3 2643.35,1068.4 2387.85,1070.8 2408.55,1070.8 2609.25,1074.27 2666.15,1074.4 2431.32,1076.41 2465.63,1076.41 2482.5,1076.41 2517.75,1076.5 2539.35,1080.7 2727.24,1081.85 2747.91,1081.85 2644.65,1089 2408.55,1091.5 2610.05,1094.93 2666.15,1095.1 2431.32,1097.08 2465.63,1097.08 2482.5,1097.08 2516.81,1097.08 2538.95,1101.35 2727.24,1102.52 2747.91,1102.52 2644.65,1109.67 2610.05,1115.6 2666.15,1115.8 2431.32,1117.75 2465.63,1117.75 2482.5,1117.75 2516.81,1117.75 2538.95,1122.05 2727.24,1123.19 2747.91,1123.19 2644.65,1130.34 2610.05,1136.27 2666.15,1136.5 2431.32,1138.42 2465.63,1138.42 2482.5,1138.42 2516.81,1138.42 2538.95,1142.7 2727.24,1143.86 2747.91,1143.86 2644.65,1151.01 2610.05,1156.94 2666.15,1157.2 2708.45,1157.6 2431.32,1159.09 2465.63,1159.09 2482.5,1159.09 2516.81,1159.09 2538.95,1163.4 2688.95,1162.9 2727.24,1164.53 2747.91,1164.53 320.08,1167.94 340.75,1167.94 361.42,1167.94 2648.45,1171.33 1736.21,1176.93 2613.05,1177.4 2431.32,1179.76 2465.63,1179.76 2482.5,1179.76 2516.81,1179.76 2561.45,1181.9 2593.05,1182.7 2665.23,1183.4 2538.95,1184.25 2685.9,1185.2 2706.57,1185.2 2727.24,1185.2 2747.91,1185.2 2623.15,1195.45 1736.21,1197.6 2431.32,1200.43 2465.63,1200.43 2482.5,1200.43 2516.81,1200.43 2582.05,1200.7 2560.65,1204.1 2538.95,1204.95 2603.95,1205.5 2638.77,1209 2657.75,1217.2 1736.21,1218.27 2678.42,1219.7 2699.09,1219.7 2719.76,1219.7 2740.43,1219.7 2760.65,1219.7 2431.32,1221.1 2465.63,1221.1 2482.5,1221.1 2516.81,1221.1 2538.95,1225.65 2559.65,1225.65 2580.35,1225.65 2602.35,1226.1 2719.76,1240.37 2740.43,1240.37 2760.65,1240.37 2431.32,1241.77 2465.63,1241.77 2482.5,1241.77 2516.81,1241.77 2668.35,1242.1 2689.05,1242.1 2539.05,1246.4 2719.76,1261.04 2740.43,1261.04 2760.65,1261.04 2431.32,1262.44 2465.63,1262.44 2482.5,1262.44 2516.81,1262.44 2538.95,1267 2719.76,1281.71 2740.43,1281.71 2760.65,1281.71 2431.32,1283.11 2465.63,1283.11 2482.5,1283.11 2516.81,1283.11 2538.95,1287.85 2719.76,1302.38 2740.43,1302.38 2760.65,1302.38 2431.32,1303.78 2465.63,1303.78 2482.5,1303.78 2516.81,1303.78 2664.55,1304.7 2687.95,1304.9 2719.76,1323.05 2740.43,1323.05 2760.65,1323.05 2431.32,1324.45 2465.63,1324.45 2482.5,1324.45 2516.81,1324.45 2664.75,1329 2686.55,1330.2 2719.76,1343.72 2740.43,1343.72 2760.65,1343.72 2431.32,1345.12 2465.63,1345.12 2482.5,1345.12 2516.81,1345.12 2665.35,1351.2 2686.15,1351.4 2719.76,1364.39 2740.43,1364.39 2760.65,1364.39 2431.32,1365.79 2465.63,1365.79 2482.5,1365.79 2516.81,1365.79 2663.65,1372.7 2691.65,1375 2719.76,1385.06 2740.43,1385.06 2760.65,1385.06 2516.81,1386.46 2644.85,1394.8 2719.76,1405.73 2740.43,1405.73 2760.65,1405.73 2431.32,1407.13 2465.63,1407.13 2482.5,1407.13 2516.81,1407.13 2658.45,1422.4 2632.95,1426.5 2719.76,1426.4 2740.43,1426.4 2760.65,1426.4 2431.32,1427.8 2465.63,1427.8 2482.5,1427.8 2516.81,1427.8 2609.05,1428.2 2681.85,1429.6 2661.35,1446.4 2719.76,1447.07 2740.43,1447.07 2760.65,1447.07 2431.32,1448.47 2465.63,1448.47 2482.5,1448.47 2516.81,1448.47 2615.05,1447.6 2639.05,1448.8 2685.45,1454.4 2597.05,1457.8 2218.17,1461.27 2576.43,1461.27 2704.05,1463.4 2431.32,1469.14 2465.63,1469.14 2482.5,1469.14 2516.81,1469.14 2422.89,1486.86 2474.07,1486.86 2525.25,1486.86 2576.43,1486.86 2702.75,1492.5 2726.81,1495.24 2747.48,1495.24 2682.85,1499.1 2433.12,1504.57 2463.83,1504.57 2484.3,1504.57 2515.01,1504.57 2448.48,1512.45 2499.66,1512.45 2576.43,1512.45 2726.81,1515.91 2747.48,1515.91 2694.85,1517.2 2673.05,1517.9 2747.75,1536.5 2706.14,1536.58 2726.81,1536.58 2685.51,1537.98 2632.05,1541.8 2665.67,1543.78 2613.55,1550.7 2647.8,1554.2 2550.84,1563.63 2629.6,1564.18 2609.81,1570.18 2706.18,1571.08 2726.85,1571.08 2747.52,1571.08 2568.55,1572.07 2589.22,1572.07 2685.62,1573.28 2533.12,1573.86 2667.15,1582.58 2525.25,1589.22 2735.15,1589.4 2756.55,1590 2649.3,1593.03 2688.06,1599.68 2630,1600.58 2708.73,1600.58 2667.51,1601.88 2533.12,1604.57 2609.81,1605.08 2568.55,1606.37 2589.22,1606.37 2727.75,1608.5 2648.7,1610.47 2748.08,1611.29 2550.84,1614.81 2630.35,1620.08 2568.55,1623.25 2589.22,1623.25 2609.89,1623.25 2533.12,1625.04 2687.65,1634.48 2708.05,1637.78 2525.25,1640.4 2667.65,1639.68 2727.15,1645.68 2747.82,1645.68 2649.6,1649.77 2680.35,1655.4 2533.12,1655.75 2630.48,1655.68 2700.45,1656.1 2568.55,1657.55 2589.22,1657.55 2609.89,1657.55 2662.25,1665.1 2550.84,1665.99 2719.45,1666.5 2739.75,1666.5 2759.55,1665.6 2568.55,1674.43 2589.22,1674.43 2609.89,1674.43 2700.45,1675.2 2533.12,1676.23 2630.48,1676.3 2680.15,1677 2649.6,1682.21 2727.15,1686.3 2747.75,1685.5 2525.25,1691.58 2667.65,1692.3 2708.05,1694.2 2687.65,1697.5 2533.12,1706.93 2568.55,1708.73 2589.22,1708.73 2609.89,1708.73 2630.35,1711.9 2550.84,1717.17 2748.08,1720.69 2648.7,1721.51 2727.75,1723.5 2568.55,1725.61 2589.22,1725.61 2533.12,1727.41 2609.81,1726.9 2667.51,1730.1 2630,1731.4 2708.73,1731.4 2688.06,1732.3 2649.3,1738.95 2733.25,1741.8 2755.25,1742.4 2525.25,1742.76 2667.15,1749.4 2533.12,1758.11 2685.62,1758.7 2568.55,1759.91 2589.22,1759.91 2706.18,1760.9 2726.85,1760.9 2747.52,1760.9 2609.81,1761.8 2550.87,1768.35 2629.6,1767.8 2647.8,1777.78 2617.45,1784.6 2665.67,1788.2 2685.51,1794 2706.14,1795.4 2726.81,1795.4 2747.48,1795.4 2717.45,1813.03 2759.55,1812.6 2677.75,1814.1 2739.45,1813.5 2697.45,1816 2738.88,1833.27 2759.55,1833.27 2717.45,1833.7 2697.65,1838.5 2716.15,1858.6 2695.05,1868.8 2737.75,1869.1 2759.45,1869.5 2710.45,1883.3 2239.22,2330.24 2259.89,2330.24 2280.56,2330.24 2301.23,2330.24 2321.9,2330.24 2342.57,2330.24 2363.24,2330.24 2383.91,2330.24 2404.58,2330.24 2218.55,2331.7 2425.25,2331.7 2197.82,2347.4 2442.55,2347.4 2218.55,2363.1 2425.25,2363.1 2239.22,2364.56 2259.89,2364.56 2280.56,2364.56 2301.23,2364.56 2321.9,2364.56 2342.57,2364.56 2363.24,2364.56 2383.91,2364.56 2404.58,2364.56 1766.05,2418.34 1786.72,2418.34 1807.39,2418.34 1828.06,2418.34 1848.73,2418.34 1869.4,2418.34 1890.07,2418.34 1910.74,2418.34 1931.41,2418.34 1952.08,2418.34 1972.75,2418.34 1993.42,2418.34 2014.09,2418.34 2034.76,2418.34 2055.43,2418.34 2076.1,2418.34 2096.77,2418.34 2117.44,2418.34 2138.11,2418.34 2158.78,2418.34 2179.45,2418.34 2200.12,2418.34 2220.79,2418.34 2241.46,2418.34 2262.13,2418.34 2282.8,2418.34 2303.47,2418.34 2324.14,2418.34 2344.81,2418.34 2365.48,2418.34 2386.15,2418.34 2406.82,2418.34 1745.38,2419.8 2427.44,2419.8 1722.45,2435.5 2443.35,2435.5 1745.38,2451.2 2427.44,2451.2 1766.05,2452.66 1786.72,2452.66 1807.39,2452.66 1828.06,2452.66 1848.73,2452.66 1869.4,2452.66 1890.07,2452.66 1910.74,2452.66 1931.41,2452.66 1952.08,2452.66 1972.75,2452.66 1993.42,2452.66 2014.09,2452.66 2034.76,2452.66 2055.43,2452.66 2076.1,2452.66 2096.77,2452.66 2117.44,2452.66 2138.11,2452.66 2158.78,2452.66 2179.45,2452.66 2200.12,2452.66 2220.79,2452.66 2241.46,2452.66 2262.13,2452.66 2282.8,2452.66 2303.47,2452.66 2324.14,2452.66 2344.81,2452.66 2365.48,2452.66 2386.15,2452.66 2406.82,2452.66
  other v3: 2101.25,1052.79 2140.61,1052.79 2101.25,1092.16 2140.61,1092.16 1619.5,1243 1653.75,1243 1688,1243 1757.37,1843.51 1757.37,1930.13
LDO_01_EN: R83.1 R84.2 U4.5 | length 104.6
  TOP w13: R84.2@2019,1013.72 2019.39,1014.11 2019.68,1014.4 2019.79,1014.4 U4.5@2082.54,1014.4
  TOP w20: R84.2@2019,1013.72 R83.1@2019,1054.52
LDO_02_EN: R46.2 R47.1 U5.6 U5.20 | length 642
  TOP w4: R47.1@1545.15,1869.5 1587.75,1869.5 1588.35,1868.9 R46.2@1588.35,1868.11 1588.35,1818.9 1623.75,1783.5 1647.75,1783.5 v1(1649.95,1785.7)
  L4-GND/SIG w5: v1(1649.95,1785.7) 1615.65,1820 1615.65,1966.2 1647.75,1998.3 1647.75,2014.6 v1(1674.25,2041.1)
  BOTTOM w4: v1(1649.95,1785.7) 1706.74,1785.7 1718,1796.96 U5.20@1718,1808.08 ; v1(1674.25,2041.1) 1674.25,2020.9 1718,1977.15 U5.6@1718,1965.56
MCU_3V3: J4.3 J6.1 R130.1 | length 3047.1
  TOP w35: v1(815.75,545) 816.25,545.5 1331.25,545.5 v1(1375.75,590) ; v1(1534.56,1800.19) 1534.56,1816.09 1494.75,1855.9 1494.75,2026.3 1556.35,2087.9 1601.75,2087.9 1636.75,2122.9 v1(1636.75,2152.4)
  L4-GND/SIG w35: v1(1375.75,590) 1375.75,590.07 1382.45,596.77 1382.45,1214.3 1338.75,1258 1338.75,1428.4 1373.45,1463.1 1373.45,1553.2 1534.56,1714.31 v1(1534.56,1800.19)
  BOTTOM w35: R130.1@1534.56,1761.21 v1(1534.56,1800.19) ; v1(1636.75,2152.4) 1636.75,2203.8 1691.15,2258.2 1742.45,2258.2 1876.23,2391.98 J4.3@1930.25,2391.98
  BOTTOM w40: J6.1@630.25,460.78 630.25,494.79 680.46,545 v1(815.75,545)
MCU_5V: J6.2 J7.3 R115.1 | length 113.2
  BOTTOM w40: v1(593.75,729.5) 593.75,727.5 630.25,691 J6.2@630.25,683.22 657.47,656 v1(670.75,656)
  other v1: 1944.75,538 1897.75,540 1887.75,575 1891.75,612 544.75,728.5 666.75,731.5
MCU_SOP0: R36.1 R93.2 | length 1743.3
  TOP w4: R93.2@1108.57,729.45 1110.89,729.45 1132.95,751.51 1132.95,820.7 v1(1136.95,824.7) ; v1(1490.75,2118) 1498.98,2126.23 R36.1@1530,2126.23
  BOTTOM w4: v1(1136.95,824.7) 1312.95,1000.7 1312.95,1164.7 1262.15,1215.5 1262.15,1257.8 1285.63,1281.28 1285.63,1290.06 1309.71,1314.14 1309.71,1325.96 1309.75,1326 1309.75,1550.1 1305.25,1554.6 1305.25,1575.4 1315.75,1585.9 1315.75,1842.3 1251.75,1906.3 1251.75,1970.5 1375.85,2094.6 1467.35,2094.6 v1(1490.75,2118)
MCU_SOP1: R35.1 R112.2 | length 2050.4
  TOP w4: R112.2@752.07,591.15 766.79,591.15 795.35,619.71 795.35,691.1 858.95,754.7 998.35,754.7 v1(1024.35,780.7) ; v1(1393.75,2126) 1394.75,2126 1394.75,2126.23 R35.1@1429.5,2126.23
  BOTTOM w4: v1(1024.35,780.7) 1113.45,869.8 1155.05,869.8 1303.95,1018.7 1303.95,1152.92 1253.15,1203.72 1253.15,1261.53 1276.63,1285.01 1276.63,1293.79 1300.71,1317.87 1300.71,1329.82 1300.75,1329.86 1300.75,1541.5 1295.85,1546.4 1295.85,1579 1306.75,1589.9 1306.75,1833.7 1242.75,1897.7 1242.75,1974.5 1393.75,2125.5 v1(1393.75,2126)
MCU_SOP2: R32.1 R101.2 | length 2731.1
  TOP w4: R101.2@469.73,690.25 469.34,690.64 456.75,703.23 456.75,868 470.75,882 748.05,882 846.65,783.4 969.15,783.4 v1(1000.55,814.8) ; v1(1348.96,2305.21) R32.1@1380.3,2305.21
  BOTTOM w4: v1(1000.55,814.8) 1035.05,814.8 1099.05,878.8 1149.05,878.8 1294.95,1024.7 1294.95,1144.76 1244.15,1195.56 1244.15,1265.26 1267.63,1288.74 1267.63,1297.52 1291.71,1321.6 1291.71,1333.55 1291.75,1333.59 1291.75,1537.5 1278.75,1550.5 1264.75,1550.5 1252.75,1562.5 1252.75,1582.6 1288.75,1618.6 1288.75,1821.1 1224.75,1885.1 1224.75,2026.11 1251.14,2052.5 1294.24,2052.5 1362.75,2121.01 1362.75,2182.5 1412.75,2232.5 1412.75,2267.5 1375.04,2305.21 v1(1348.96,2305.21)
MISO1: R6.2 R7.2 U14.1 | length 1407
  TOP w4: U14.1@1162.65,1292.68 1162.65,1316.11 1172.19,1325.65 v1(1200.62,1325.65) ; R6.2@1230.8,2392.23 R7.2@1264,2392.23 1264,2358.25 v1(1277.75,2344.5)
  BOTTOM w4: v1(1200.62,1325.65) 1214.1,1325.65 1234.35,1305.4 1246.43,1305.4 1252.45,1311.42 1252.45,1333.26 1273.22,1354.03 1273.22,1370.95 1213.58,1430.59 1213.58,1571.93 1251.65,1610 1251.65,1741.4 1226.45,1766.6 1226.45,1855.67 1188.97,1893.15 1188.97,1978.89 1203.75,1993.67 1203.75,2031.5 1285.75,2113.5 1285.75,2205.5 1326.45,2246.2 1326.45,2270.84 1307.79,2289.5 1295.75,2289.5 1277.75,2307.5 v1(1277.75,2344.5)
MOSI1: R4.2 R28.1 U14.4 | length 2092.4
  TOP w4: R28.1@1034.25,2304.89 1019.75,2319.39 1019.75,2345.5 1026.75,2352.5 v1(1070.75,2352.5) 1070.75,2458.72 1077.76,2465.73 1092.23,2465.73 1100.02,2457.94 1100.02,2396.91 1104.7,2392.23 R4.2@1125.3,2392.23 ; U14.4@1209.89,1290.71 1209.89,1276.91 1214.31,1272.49 1232.31,1272.49 1238.14,1272.49 1232.31,1278.32 v1(1232.31,1278.45)
  L3-GND/SIG w4: v1(1232.31,1278.45) 1234.92,1278.45 v1@1239,1274.37
  BOTTOM w4: v1(1070.75,2352.5) 1037.8,2319.55 994.1,2319.55 987.93,2325.72 987.93,2341.22 983.35,2345.8 969.59,2345.8 965.01,2341.22 965.01,2325.57 958.99,2319.55 923.08,2319.55 896.75,2293.22 896.75,2280.83 906.38,2271.2 941.7,2271.2 948.63,2264.27 948.63,2242.21 942.18,2235.76 900.12,2235.76 896.75,2232.39 896.75,2043.64 856.64,2003.53 856.64,1971.61 866.34,1961.91 887.35,1961.91 896.67,1971.23 896.67,1993.31 907.46,2004.1 916.27,2004.1 926.06,1994.31 926.06,1971.72 935.87,1961.91 947.65,1961.91 1010.13,1899.43 1042.02,1899.43 1059.12,1882.33 1059.12,1838.9 1055.05,1834.83 1055.05,1820.17 1074.63,1800.59 1122.39,1800.59 1206.65,1716.33 1206.65,1617.48 1183.11,1593.94 1183.11,1333.17 1182.92,1332.98 1182.92,1318.09 1226.64,1274.37 1230.72,1278.45 v1(1232.31,1278.45)
NetC1_2: C1.2 C2.2 R37.2 U1.8 | length 168.2
  TOP w15: U1.8@2090.08,2184.68 2127.56,2184.68 2140.14,2172.1 C2.2@2147.65,2172.1
  TOP w20: C2.2@2147.65,2172.1 2147.84,2171.91 2149.15,2170.6 2199.35,2170.6 2199.75,2171 R37.2@2252.25,2171
NetC16_2: C16.2 R78.1 U3.3 | length 230.9
  TOP w20: C16.2@1091.65,1082.5 1091.65,1042.5 R78.1@1092.43,1042.5 1127.75,1042.5 1194.06,1108.81 U3.3@1194.06,1168.83 U3.3@1194.06,1169.81
NetC18_1: C18.1 R81.2 R82.1 U4.3 | length 156
  TOP w13: C18.1@2101.12,1189.37 2108.13,1182.36 U4.3@2108.13,1130.54
  TOP w15: R81.2@2081.54,1239.67 R81.2@2082.33,1239.67 2118.38,1239.67 2118.38,1206.62 C18.1@2101.12,1189.37
NetC22_2: C22.2 U4.6 | length 96.1
  TOP w13: 2108.13,971.38 U4.6@2108.13,1014.4
  TOP w15: C22.2@2062.72,952.77 2062.95,953 2089.75,953 2108.13,971.38
NetC24_2: C24.2 R85.1 R87.2 | length 129.4
  TOP w4: R87.2@1179.45,835 1195.35,835 1199.25,838.9 1199.25,853.9 1218.25,872.9 1219.85,872.9 1221.45,872.9 1240.75,853.6 1240.75,840.5 1246.85,834.4 R85.1@1260.75,834.4
NetC26_1: C26.1 C27.1 D3.1 F1.1 FB1.1 FB2.1
NetC28_1: C28.1 R121.2 R122.1 U5.10 | length 138.7
  BOTTOM w10: U5.10@1796.74,1965.56 1796.74,1980.04 1816.35,1999.65 1816.35,2014.14 R122.1@1816.35,2014.92
  BOTTOM w12: R122.1@1816.35,2014.14 R122.1@1817.13,2014.92
  BOTTOM w20: R121.2@1778.02,2014.49 1778.45,2014.92 R122.1@1816.35,2014.92 1817.13,2014.92 1816.45,2015.6 C28.1@1816.45,2055.5
NetC29_2: C29.2 U5.7 | length 102.2
  BOTTOM w10: C29.2@1712.22,2057.25 C29.2@1712.22,2056.86 1712.22,2013.03 1737.68,1987.57 U5.7@1737.68,1965.56
NetC44_2: C44.2 U5.19 | length 59.9
  BOTTOM w10: C44.2@1708.92,1760.05 1709.11,1760.24 1737.68,1788.81 U5.19@1737.68,1808.08
NetC46_1: C46.1 R131.1 R132.2 U5.16 | length 147.1
  BOTTOM w10: R132.2@1770.69,1759.28 1773.22,1759.75 1771.22,1759.75 R132.2@1773.22,1761.75 ; R132.2@1773.22,1760.54 R132.2@1773.22,1761.75 ; U5.16@1796.74,1808.08 1796.74,1798.16 1773.22,1774.64 R132.2@1773.22,1761.75 ; C46.1@1811.95,1719.02 C46.1@1812.59,1719.66
  BOTTOM w20: R132.2@1770.69,1759.28 R131.1@1811.81,1759.28 1812.59,1759.28 C46.1@1812.59,1719.66
NetC49_2: C49.2 R134.1 U6.68 | length 104.2
  BOTTOM w7: U6.68@917.69,1607.39 974.21,1607.39 978.11,1603.49 R134.1@978.5,1603.1
  BOTTOM w20: C49.2@977.8,1644.4 978.5,1643.7 R134.1@978.5,1603.1
NetC63_2: C63.2 U6.88 Y2.1 | length 251.3
  BOTTOM w4: U6.88@917.69,1292.43 919.12,1291 1018.74,1291 1046.96,1262.78 1049.4,1262.78 1079.3,1292.68 1079.3,1346.36 C63.2@1071.31,1354.35
NetC66_2: C66.2 C67.2 R140.1 U6.9 U7.1 | length 250.2
  BOTTOM w7: 269.42,1292.43 U6.9@311.39,1292.43
  BOTTOM w15: C66.2@249.24,1292.6 C66.2@249.63,1292.6 269.25,1292.6 269.42,1292.43
  BOTTOM w20: U7.1@156.11,1376.99 U7.1@158.07,1376.99 176.75,1376.99 191.72,1362.02 R140.1@210.71,1362.02 211.5,1362.02 211.5,1349.25 249.24,1311.51 249.24,1292.6 249.24,1251.36 C67.2@249.3,1251.3
NetC70_2: C70.2 U6.89 Y2.3 | length 403.5
  BOTTOM w4: U6.89@917.69,1276.68 951.07,1276.68 1003.45,1224.3 1003.45,1152.38 1014.36,1141.47 1024.62,1141.47 1044.92,1121.18 1059.56,1121.18 1074.79,1136.41 1100.86,1136.41 1114.57,1122.7 C70.2@1118.25,1122.7 1136.02,1140.47 1136.02,1184.08 Y2.3@1136.02,1199.78
NetC71_2: C71.2 R154.1 U6.96 | length 174.6
  TOP w20: v1(853.75,1153) 866.39,1153 886.39,1173 C71.2@897.06,1173 C71.2@897.45,1173 ; R154.1@898.75,1118.18 C71.2@898.75,1171.31
  BOTTOM w7: v1(853.75,1153) 867.2,1166.45 U6.96@917.69,1166.45
NetC78_1: C78.1 R156.1 R157.2 U9.5 | length 394
  TOP w20: v1(165.75,1069) 165.75,1014.4 214.75,965.4 214.75,862 v1(227.75,849)
  BOTTOM w15: U9.5@203.97,835.82 214.57,835.82 v1(227.75,849)
  BOTTOM w20: v1(165.75,1069) 166.75,1069 169.85,1065.9 C78.1@169.85,1041.33 C78.1@169.85,1040.95 ; v1(227.75,849) R156.1@260.78,882 ; R156.1@260.78,882 260.78,882.79 301.61,882.79 R157.2@301.95,882.45
NetC79_2: C79.2 C80.2 R176.1 U9.1 U9.2 | length 211.7
  TOP w30: v1(63.75,963) 67.75,963 70.5,965.75 70.75,966 98.75,938 R176.1@98.75,937.5
  BOTTOM w15: C79.2@128.37,1002.05 128.18,1001.86 128.02,1001.7 127.19,1000.87 127.19,953.94 U9.2@152.78,953.94
  BOTTOM w20: 70.75,985.1 87.16,1001.51 87.35,1001.7 C79.2@128.02,1001.7
  BOTTOM w25: v1(63.75,963) 63.75,978.1 70.75,985.1
NetC85_2: C85.2 C88.1 P7.2 R61.2 U11.3 U11.4 | length 972.9
  TOP w10: 481.35,1088.1 506.55,1062.9 C88.1@609.07,1062.9 609.45,1062.9 609.65,1063.1 R61.2@609.65,1103.6
  L4-GND/SIG w20: P7.2@274.69,1908.65 274.69,1861.56 351.75,1784.5 351.75,1586.5 304.35,1539.1 304.35,1345.1 380.55,1268.9 381.85,1268.9 397.65,1253.1 v1(397.65,1206)
  other v1: 395.65,1170
NetC88_2: C88.2 R61.1 R193.2 U11.5 | length 145
  TOP w4: U11.5@598.71,1158.61 647.65,1158.61 647.45,1158.41 647.45,1157.82 647.45,1103.6 647.45,1063.5 C88.2@648.05,1062.9
NetC91_2: C91.2 R196.1 U12.5 | length 135.4
  TOP w12: U12.5@1765.38,1187.4 1820.65,1187.4 C91.2@1821.15,1187.9
  TOP w20: C91.2@1821.15,1187.9 1866.65,1187.9 1890.26,1164.29 R196.1@1890.65,1163.9
NetC92_2: C92.2 R200.1 U13.5 | length 94.9
  TOP w12: U13.5@342.75,1138.77 342.75,1117.3 324.3,1098.85 331.15,1092 360.35,1092 C92.2@366.35,1098
NetC93_2: C93.2 R202.1 | length 40.2
  BOTTOM w20: C93.2@1454.45,1417.1 1454.85,1417.5 R202.1@1494.45,1417.5
NetC94_2: C94.2 R203.1 | length 37.4
  BOTTOM w20: C94.2@1814.05,1380.1 C94.2@1814.05,1380.49 1814.05,1416.61 1814.05,1417.2 R203.1@1814.25,1417.4
NetC95_2: C95.2 R204.1 | length 40.4
  BOTTOM w20: C95.2@1453.15,1048 1453.34,1048.19 R204.1@1493.45,1048.2
NetC96_2: C96.2 R205.1 | length 41.3
  BOTTOM w20: R205.1@1836.65,1051.7 1877.65,1051.7 C96.2@1877.85,1051.9
NetD2_1: D2.1 R80.2 | length 67.8
  TOP w10: D2.1@139.05,1268.56 139.64,1267.97 D2.1@140.24,1267.97 D2.1@143.09,1267.97
  TOP w20: R80.2@75.5,1268.56 D2.1@139.05,1268.56
NetDS1_1: DS1.1 R90.1 | length 200
  TOP w20: DS1.1@237.46,743.13 282.88,743.13 312.75,773 312.75,871.85 303.6,881 R90.1@303.21,881.39
NetDS2_1: DS2.1 R100.1 | length 59.8
  TOP w20: R100.1@345.66,691.25 348.75,694.33 348.75,736.23 DS2.1@358.35,745.83
NetDS3_1: DS3.1 R103.1 | length 84.2
  TOP w20: DS3.1@119.78,742.81 119.78,713.97 129.22,704.53 R103.1@129.22,662.57
NetDS3_2: DS3.2 Q1.3 | length 175.9
  TOP w20: DS3.2@119.78,805.81 132.94,805.81 175.65,763.1 175.65,728.21 222.35,681.51 Q1.3@223.33,680.53
NetDS4_1: DS4.1 R117.1 | length 54.4
  TOP w20: DS4.1@358.35,538.42 407.91,538.42 R117.1@411.36,534.96
NetDS4_2: DS4.2 Q2.3 | length 183.7
  TOP w20: v1(238.75,639) 277.06,639 317.6,598.46 DS4.2@358.35,598.46
  BOTTOM w20: Q2.3@223.37,679.95 223.37,654.38 v1(238.75,639)
NetF1_2: F1.2 P6.1
NetJ1_1: J1.1 J1.2 J1.3 R34.1
NetJ1_4: J1.4 R67.1 | length 169.2
  TOP w4: J1.4@1182.55,1935.77 1182.55,1893.9 1229.75,1846.7 1229.75,1789.96 R67.1@1227,1787.21
NetJ1_5: J1.5 R29.2 | length 265.8
  TOP w4: R29.2@1066.58,2279.23 1066.58,2257.67 v1(1071.75,2252.5) ; J1.5@1162.86,2161.75 1162.86,2208.61 1181.75,2227.5 v1(1181.75,2258.5)
  BOTTOM w4: v1(1071.75,2252.5) 1101.75,2282.5 1157.75,2282.5 v1(1181.75,2258.5)
NetJ1_6: J1.6 R66.1 | length 161.7
  TOP w4: J1.6@1162.86,1935.77 1162.86,1893.9 1182.75,1874.01 1182.75,1798.96 R66.1@1194.5,1787.21
NetJ1_7: J1.7 R17.2 | length 126.7
  TOP w4: J1.7@1143.18,2161.75 1143.18,2202.93 1163,2222.75 R17.2@1163,2280.23
NetJ1_8: J1.8 R65.1 | length 159.6
  TOP w4: J1.8@1143.18,1935.77 1143.18,1894.58 1165.95,1871.81 1165.95,1791.16 R65.1@1162,1787.21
